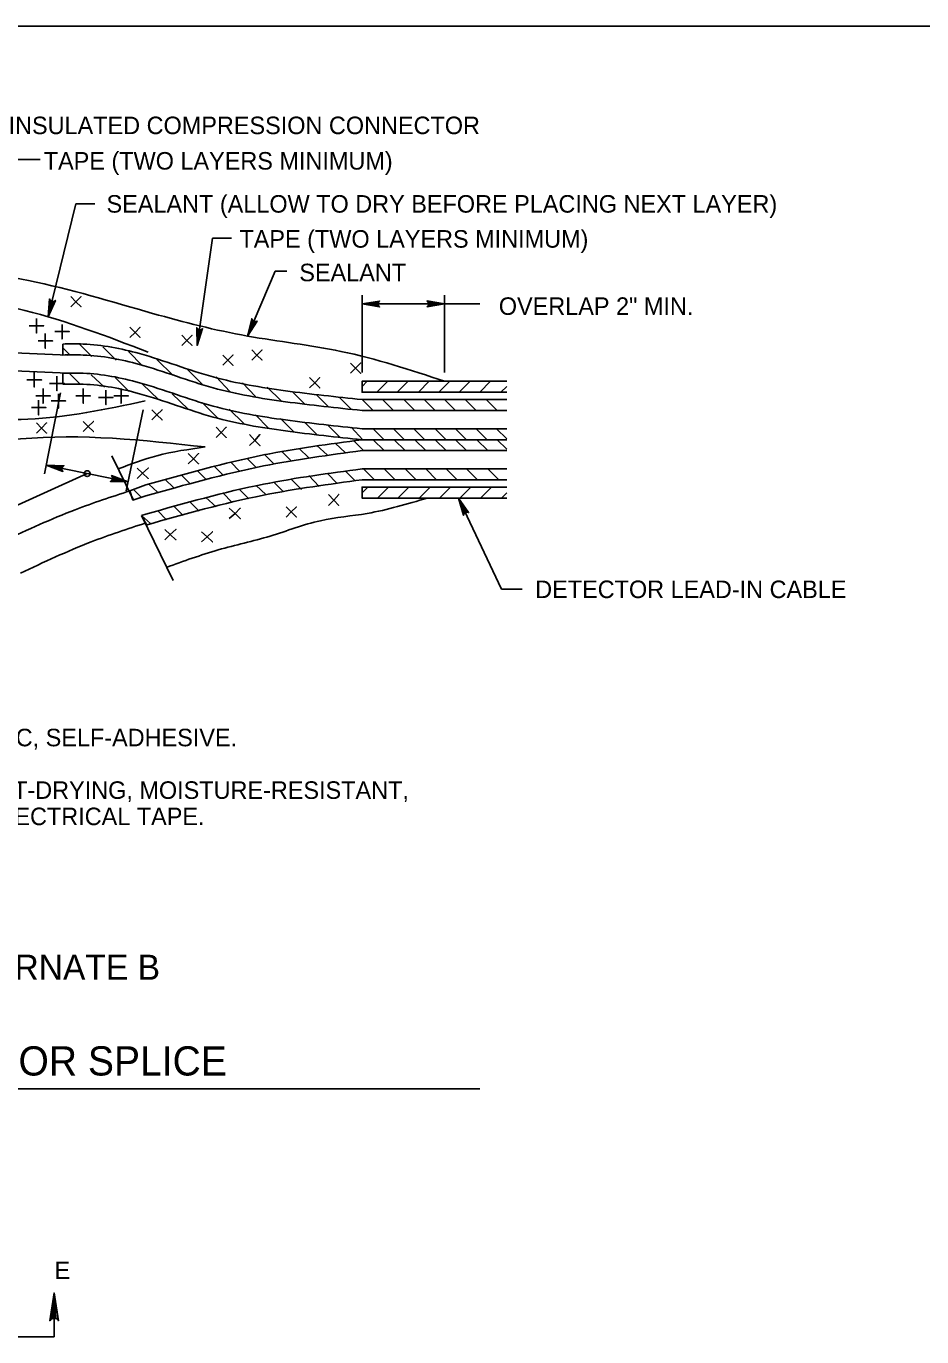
# Model space of a CAD drawing. Extents: x 2709 to 3899, y 22 to 1210.
# Drawn here: x 3103.3 to 3256.6, y 376.8 to 601.2 of the extents above; entities that cross this region are included whole.
import ezdxf

# ---------------------------------------------------------------- set-up
doc = ezdxf.new("R2010")
doc.units = 0
for name, color, linetype in [('1', 7, 'Continuous'), ('2', 7, 'Continuous'), ('3', 7, 'Continuous')]:
    doc.layers.add(name, color=color, linetype=linetype)

# ---------------------------------------------------------------- blocks, each defined once
blk = doc.blocks.new('RARROW')
at = {"layer": '3'}
blk.add_lwpolyline([(-2.2695, 0.285), (-2.184875, 0.12075), (0, 0), (-2.2695, 0.285), (-2.38575, 0.384625), (0, 0), (-2.183125, -0.108), (-2.262875, -0.2705), (0, 0), (-2.38575, -0.379125), (-2.262875, -0.2705)], dxfattribs=at)

msp = doc.modelspace()

# ---------------------------------------------------------------- linework, layer by layer
at = {"layer": '1'}
for p, q in [((2748.86, 601.17), (3534.86, 601.17)), ((3040.51, 419.23), (3180.88, 419.23))]:
    msp.add_line(p, q, dxfattribs=at)
at = {"layer": '2'}
for p, q in [((3101.75, 578.37), (3105.63, 578.37)), ((3107.03, 551.43), (3111.75, 570.75)), ((3111.75, 570.75), (3115, 570.75)), ((3132.5, 546.5), (3135.13, 564.87)), ((3135.13, 564.87), (3138.38, 564.87)), ((3141.13, 548.12), (3145.88, 559.25)), ((3145.88, 559.25), (3147.88, 559.25)), ((3160.75, 541.87), (3160.75, 555.12)), ((3174.88, 541.87), (3174.88, 555.12)), ((3160.75, 553.62), (3174.88, 553.62)), ((3180.9, 553.62), (3174.88, 553.62)), ((3110.38, 544.87), (3098.5, 545.37)), ((3109.5, 544.87), (3109.5, 546.75)), ((3110.38, 541.75), (3098.5, 542.25)), ((3109.5, 539.87), (3109.5, 541.75)), ((3109.13, 538.37), (3106.38, 524.5)), ((3123.25, 535.5), (3120.38, 521.62)), ((3117.88, 527.62), (3121.63, 520)), ((3106.67, 525.99), (3120.69, 523.13)), ((3113.68, 524.56), (3080.69, 509.66)), ((3121, 521.62), (3123.75, 522.62)), ((3121.5, 520), (3121, 521.62)), ((3123.75, 520.75), (3121.5, 520)), ((3177.25, 520.37), (3184.63, 504.75)), ((3123, 517.37), (3123.75, 517.62)), ((3123.88, 515.75), (3123, 517.37)), ((3123, 517.37), (3128.38, 506.25)), ((3184.63, 504.75), (3188.13, 504.75))]:
    msp.add_line(p, q, dxfattribs=at)
for points in [[(3110.88, 554.87), (3111.75, 554), (3112.63, 553.12), (3111.75, 554), (3112.63, 554.87), (3111.75, 554), (3110.88, 553.12)], [(3105, 551.12), (3105, 549.87), (3105, 548.62), (3105, 549.87), (3106.25, 549.87), (3105, 549.87), (3103.75, 549.87)], [(3109.38, 550.12), (3109.38, 548.87), (3109.38, 547.62), (3109.38, 548.87), (3110.63, 548.87), (3109.38, 548.87), (3108.13, 548.87)], [(3106.52, 548.54), (3106.52, 547.29), (3106.52, 546.04), (3106.52, 547.29), (3107.77, 547.29), (3106.52, 547.29), (3105.27, 547.29)], [(3121, 549.62), (3121.88, 548.75), (3122.75, 547.87), (3121.88, 548.75), (3122.75, 549.62), (3121.88, 548.75), (3121, 547.87)], [(3129.88, 548.25), (3130.75, 547.37), (3131.63, 546.5), (3130.75, 547.37), (3131.63, 548.25), (3130.75, 547.37), (3129.88, 546.5)], [(3110.75, 544.87), (3109.5, 546.12)], [(3114.5, 544.62), (3112.38, 546.75)], [(3118.63, 544), (3116.38, 546.25)], [(3123.13, 543), (3120.75, 545.5)], [(3141.88, 545.75), (3142.75, 544.87), (3143.63, 544), (3142.75, 544.87), (3143.63, 545.75), (3142.75, 544.87), (3141.88, 544)], [(3128.38, 541.37), (3125.63, 544.12)], [(3136.88, 544.87), (3137.75, 544), (3138.63, 543.12), (3137.75, 544), (3138.63, 544.87), (3137.75, 544), (3136.88, 543.12)], [(3158.75, 543.5), (3159.63, 542.62), (3160.5, 541.75), (3159.63, 542.62), (3160.5, 543.5), (3159.63, 542.62), (3158.75, 541.75)], [(3104.63, 541.87), (3104.63, 540.62), (3104.63, 539.37), (3104.63, 540.62), (3105.88, 540.62), (3104.63, 540.62), (3103.38, 540.62)], [(3108.5, 541.25), (3108.5, 540), (3108.5, 538.75), (3108.5, 540), (3109.75, 540), (3108.5, 540), (3107.25, 540)], [(3112.5, 539.87), (3110.63, 541.75)], [(3116.63, 539.37), (3114.38, 541.5)], [(3120.88, 538.62), (3118.5, 541)], [(3133.38, 539.87), (3130.75, 542.5)], [(3138.13, 538.62), (3135.75, 541.12)], [(3151.75, 541), (3152.63, 540.12), (3153.5, 539.25), (3152.63, 540.12), (3153.5, 541), (3152.63, 540.12), (3151.75, 539.25)], [(3106.13, 539.12), (3106.13, 537.87), (3106.13, 536.62), (3106.13, 537.87), (3107.38, 537.87), (3106.13, 537.87), (3104.88, 537.87)], [(3113, 539.12), (3113, 537.87), (3113, 536.62), (3113, 537.87), (3114.25, 537.87), (3113, 537.87), (3111.75, 537.87)], [(3116.88, 538.87), (3116.88, 537.62), (3116.88, 536.37), (3116.88, 537.62), (3118.13, 537.62), (3116.88, 537.62), (3115.63, 537.62)], [(3119.5, 539.12), (3119.5, 537.87), (3119.5, 536.62), (3119.5, 537.87), (3120.75, 537.87), (3119.5, 537.87), (3118.25, 537.87)], [(3125.88, 537.25), (3123.13, 539.87)], [(3142.5, 537.75), (3140.25, 540.12)], [(3146.88, 537), (3144.5, 539.37)], [(3150.88, 536.5), (3148.75, 538.62)], [(3160.75, 539.5), (3161.63, 540.37)], [(3185.5, 540.37), (3160.75, 540.37), (3160.75, 538.5), (3185.5, 538.5)], [(3163.25, 538.5), (3165.13, 540.37)], [(3166.75, 538.5), (3168.63, 540.37)], [(3170.38, 538.5), (3172.25, 540.37)], [(3173.88, 538.5), (3175.75, 540.37)], [(3177.38, 538.5), (3179.25, 540.37)], [(3180.88, 538.5), (3182.75, 540.37)], [(3184.5, 538.5), (3185.5, 539.5)], [(3105.38, 537.12), (3105.38, 535.87), (3105.38, 534.62), (3105.38, 535.87), (3106.63, 535.87), (3105.38, 535.87), (3104.13, 535.87)], [(3108.75, 538.25), (3108.75, 537), (3108.75, 535.75), (3108.75, 537), (3110, 537), (3108.75, 537), (3107.5, 537)], [(3131, 535.62), (3128.25, 538.25)], [(3136, 534.12), (3133.38, 536.75)], [(3155, 536), (3152.88, 538.12)], [(3158.88, 535.62), (3156.88, 537.62)], [(3162.63, 535.37), (3160.75, 537.25)], [(3160.75, 537.25), (3160.75, 537.25), (3185.5, 537.25)], [(3166.13, 535.37), (3164.25, 537.25)], [(3169.75, 535.37), (3167.88, 537.25)], [(3173.25, 535.37), (3171.38, 537.25)], [(3176.75, 535.37), (3174.88, 537.25)], [(3180.25, 535.37), (3178.38, 537.25)], [(3183.88, 535.37), (3182, 537.25)], [(3185.5, 537.25), (3185.5, 537.25)], [(3124.75, 535.5), (3125.63, 534.62), (3126.5, 533.75), (3125.63, 534.62), (3126.5, 535.5), (3125.63, 534.62), (3124.75, 533.75)], [(3140.5, 533.12), (3138, 535.62)], [(3144.75, 532.37), (3142.5, 534.62)], [(3185.5, 535.37), (3160.75, 535.37)], [(3105, 533.25), (3105.88, 532.37), (3106.75, 531.5), (3105.88, 532.37), (3106.75, 533.25), (3105.88, 532.37), (3105, 531.5)], [(3113, 533.5), (3113.88, 532.62), (3114.75, 531.75), (3113.88, 532.62), (3114.75, 533.5), (3113.88, 532.62), (3113, 531.75)], [(3135.75, 532.5), (3136.63, 531.62), (3137.5, 530.75), (3136.63, 531.62), (3137.5, 532.5), (3136.63, 531.62), (3135.75, 530.75)], [(3149, 531.75), (3146.75, 534)], [(3153, 531.25), (3150.88, 533.37)], [(3157, 530.75), (3154.88, 532.87)], [(3160.88, 530.37), (3158.88, 532.5)], [(3160.75, 532.25), (3160.75, 532.25), (3185.5, 532.25)], [(3164.5, 530.37), (3162.63, 532.25)], [(3168, 530.37), (3166.13, 532.25)], [(3171.5, 530.37), (3169.63, 532.25)], [(3175.13, 530.37), (3173.25, 532.25)], [(3178.63, 530.37), (3176.75, 532.25)], [(3182.13, 530.37), (3180.25, 532.25)], [(3185.5, 530.5), (3183.75, 532.25)], [(3141.5, 531.25), (3142.38, 530.25), (3143.25, 529.37), (3142.38, 530.25), (3143.25, 531.25), (3142.38, 530.25), (3141.5, 529.37)], [(3157.88, 528.12), (3156.13, 529.75)], [(3161, 528.5), (3159.25, 530.25)], [(3160.75, 530.37), (3160.75, 530.37), (3185.5, 530.37)], [(3185.5, 530.37), (3160.75, 530.37)], [(3164.5, 528.5), (3162.63, 530.37)], [(3168.13, 528.5), (3166.25, 530.37)], [(3171.63, 528.5), (3169.75, 530.37)], [(3175.13, 528.5), (3173.25, 530.37)], [(3178.63, 528.5), (3176.75, 530.37)], [(3182.25, 528.5), (3180.38, 530.37)], [(3185.5, 528.75), (3183.88, 530.37)], [(3131, 528), (3131.88, 527.12), (3132.75, 526.25), (3131.88, 527.12), (3132.75, 528), (3131.88, 527.12), (3131, 526.25)], [(3145.63, 526.25), (3144, 527.87)], [(3148.63, 526.75), (3147, 528.37)], [(3151.63, 527.25), (3150, 528.87)], [(3154.75, 527.75), (3153, 529.37)], [(3185.5, 528.5), (3160.75, 528.5)], [(3122.25, 525.5), (3123.13, 524.62), (3124.13, 523.75), (3123.13, 524.62), (3124.13, 525.5), (3123.13, 524.62), (3122.25, 523.75)], [(3134, 523.62), (3132.5, 525.12)], [(3136.88, 524.37), (3135.38, 525.87)], [(3139.75, 525), (3138.25, 526.5)], [(3142.63, 525.62), (3141.13, 527.12)], [(3160.75, 525.37), (3160.75, 525.37), (3185.5, 525.37)], [(3162.88, 523.5), (3161, 525.37)], [(3166.38, 523.5), (3164.5, 525.37)], [(3170, 523.5), (3168.13, 525.37)], [(3173.5, 523.5), (3171.63, 525.37)], [(3177, 523.5), (3175.13, 525.37)], [(3180.5, 523.5), (3178.63, 525.37)], [(3184.13, 523.5), (3182.25, 525.37)], [(3128.5, 522.12), (3127, 523.62)], [(3131.25, 522.87), (3129.75, 524.37)], [(3147.25, 521.5), (3145.63, 523.12)], [(3150.38, 521.87), (3148.63, 523.62)], [(3153.38, 522.37), (3151.63, 524.25)], [(3156.5, 522.87), (3154.75, 524.62)], [(3159.5, 523.37), (3157.88, 525)], [(3185.5, 523.5), (3160.75, 523.5)], [(3123, 520.5), (3121.63, 521.87)], [(3125.75, 521.37), (3124.25, 522.75)], [(3138.5, 519.62), (3136.88, 521.25)], [(3141.38, 520.25), (3139.75, 521.87)], [(3144.25, 521), (3142.63, 522.5)], [(3155, 521), (3155.88, 520), (3156.75, 519.12), (3155.88, 520), (3156.75, 521), (3155.88, 520), (3155, 519.12)], [(3160.75, 521.25), (3161.75, 522.25)], [(3185.5, 520.37), (3160.75, 520.37), (3160.75, 522.25), (3185.5, 522.25)], [(3163.38, 520.37), (3165.25, 522.25)], [(3166.88, 520.37), (3168.75, 522.25)], [(3170.5, 520.37), (3172.38, 522.25)], [(3174, 520.37), (3175.88, 522.25)], [(3177.5, 520.37), (3179.38, 522.25)], [(3181, 520.37), (3182.88, 522.25)], [(3184.63, 520.37), (3185.5, 521.25)], [(3130.13, 517.37), (3128.5, 519)], [(3132.88, 518.12), (3131.25, 519.75)], [(3135.75, 518.87), (3134, 520.5)], [(3138, 518.62), (3139, 517.75), (3139.88, 516.87), (3139, 517.75), (3139.88, 518.62), (3139, 517.75), (3138, 516.87)], [(3147.75, 518.87), (3148.63, 518), (3149.5, 517.12), (3148.63, 518), (3149.5, 518.87), (3148.63, 518), (3147.75, 517.12)], [(3124.5, 516), (3123, 517.37)], [(3127.25, 516.62), (3125.75, 518.25)], [(3127, 515), (3127.88, 514.12), (3128.88, 513.25), (3127.88, 514.12), (3128.88, 515), (3127.88, 514.12), (3127, 513.25)], [(3133.25, 514.62), (3134.25, 513.75), (3135.13, 512.87), (3134.25, 513.75), (3135.13, 514.62), (3134.25, 513.75), (3133.25, 512.87)], [(3099.9, 376.76), (3108.03, 376.76), (3108.03, 384.26)], [(3107.53, 379.76), (3107.78, 379.89), (3108.03, 384.26), (3107.53, 379.76), (3107.28, 379.51), (3108.03, 384.26), (3108.28, 379.89), (3108.65, 379.76), (3108.03, 384.26), (3108.78, 379.51), (3108.65, 379.76)]]:
    msp.add_lwpolyline(points, dxfattribs=at)
msp.add_circle((3113.68, 524.56), 0.5, dxfattribs=at)
msp.add_circle((3113.68, 524.56), 0.5, dxfattribs=at)
for points in [[(3042.13, 550.87), (3065.5, 558.5), (3084.63, 559.75), (3103.63, 557.62), (3124.88, 552), (3141.13, 548.12), (3157.13, 545.5), (3174.88, 540.37)], [(3055.13, 548.5), (3069.5, 554), (3085, 555.12), (3103, 552.5), (3124.13, 545.37)], [(3109.5, 546.75), (3113, 546.75), (3122.63, 545.12), (3135.25, 541.12), (3147.63, 538.75), (3160.75, 537.25)], [(3160.75, 535.37), (3147.63, 536.87), (3135.25, 539.25), (3122.63, 543.25), (3113, 544.87), (3109.5, 544.87)], [(3109.5, 541.75), (3113, 541.75), (3122.63, 540.12), (3135.25, 536.12), (3147.63, 533.75), (3160.75, 532.25)], [(3055, 540.37), (3070, 535.5), (3085.88, 534.37), (3103.5, 533.87), (3123.63, 537)], [(3160.75, 530.37), (3147.63, 531.87), (3135.25, 534.25), (3122.63, 538.25), (3113, 539.87), (3109.5, 539.87)], [(3039.75, 537.87), (3063.13, 529.5), (3087.75, 528.62), (3102.25, 530.5), (3133.88, 529.12)], [(3123.75, 522.62), (3143.88, 527.75), (3160.75, 530.37)], [(3133.88, 529.12), (3125.63, 527.62), (3119, 525.37)], [(3160.75, 528.5), (3143.88, 525.87), (3123.75, 520.75)], [(3123.75, 517.62), (3143.88, 522.75), (3160.75, 525.37)], [(3160.75, 523.5), (3143.88, 520.87), (3123.75, 515.75)], [(3121, 521.62), (3111.63, 518.37), (3099.5, 513.12)], [(3171.88, 520.37), (3161.63, 517.75), (3153.63, 516.5), (3145, 513.87), (3136.13, 511.5), (3127.25, 508.5)], [(3123.75, 516.12), (3114.38, 512.87), (3102.25, 507.5)]]:
    msp.add_spline(points, degree=3, dxfattribs=at)

# ---------------------------------------------------------------- block references
at = {"layer": '2', "xscale": 1.2574347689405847, "yscale": 1.3092961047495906}
for p, rotation in [((3107.03, 551.43), -103.79161221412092), ((3160.75, 553.62), 180), ((3141.13, 548.12), -113.33531943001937), ((3132.5, 546.5), -98.52721759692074), ((3106.67, 525.99), 169.04260156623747), ((3120.69, 523.13), -11.452924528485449), ((3177.25, 520.37), 115.47227386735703)]:
    msp.add_blockref('RARROW', p, dxfattribs=dict(at, rotation=rotation))
msp.add_blockref('RARROW', (3174.88, 553.62), dxfattribs=at)

# ---------------------------------------------------------------- texts
at = {"layer": '2'}
for s, height, p in [('INSULATED COMPRESSION CONNECTOR', 3, (3100.23, 582.69)), ('TAPE (TWO LAYERS MINIMUM)', 3, (3106.25, 576.62)), ('SEALANT (ALLOW TO DRY BEFORE PLACING NEXT LAYER)', 3, (3117, 569.25)), ('TAPE (TWO LAYERS MINIMUM)', 3, (3139.75, 563.25)), ('SEALANT', 3, (3150, 557.5)), ('OVERLAP 2" MIN.', 3, (3184.15, 551.74)), ('DETECTOR LEAD-IN CABLE', 3, (3190.38, 503.25)), ('TAPE   - ELECTRICAL GRADE, PLASTIC, SELF-ADHESIVE.', 3, (3029, 477.87)), ('SEALANT - ELECTRICAL GRADE, FAST-DRYING, MOISTURE-RESISTANT,', 3, (3029, 468.87)), ('          COMPATIBLE WITH PLASTIC ELECTRICAL TAPE.', 3, (3029, 464.37)), ('ALTERNATE B', 4.3, (3086.86, 437.89)), ('DETECTOR SPLICE', 5, (3075.18, 421.5)), ('E', 3, (3108.1, 386.64))]:
    msp.add_text(s, height=height, dxfattribs=at).set_placement(p)

doc.saveas('drawing.dxf')
